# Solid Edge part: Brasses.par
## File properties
Author: Vicky Raina
Template: normal.par
Last saved by: Administrator
Revision: 4
Application: Solid Edge
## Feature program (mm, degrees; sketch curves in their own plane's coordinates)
sketch for "unnamed RevolvedProtrusion 1" plane through (0, 0, 0) normal (0, -1, 0) x-axis (1, 0, 0)
  line (-32.5, 0) -> (-32.5, 32)
  line (-32.5, 32) -> (-23, 32)
  line (-23, 32) -> (-23, 24)
  line (-23, 24) -> (-14, 24)
  line (-14, 24) -> (-14, 22)
  line (-14, 22) -> (14, 22)
  line (14, 22) -> (14, 24)
  line (14, 24) -> (23, 24)
  line (23, 24) -> (23, 32)
  line (23, 32) -> (32.5, 32)
  line (32.5, 32) -> (32.5, 0)
  line (32.5, 0) -> (-32.5, 0)
revolve "unnamed RevolvedProtrusion 1" add finite 360 deg
sketch for "unnamed Protrusion 1" plane through (0, 0, 0) normal (0, 0, 1) x-axis (1, 0, 0)
  circle centre (0, 0) radius 4
extrude "unnamed Protrusion 1" add finite 30 along -normal
sketch for "unnamed Hole 1" plane through (0, 0, -30) normal (0, 0, -1) x-axis (1, 0, 0)
  hole centre (0, 0) bore radius 3
hole "unnamed Hole 1" through
sketch for "unnamed Hole 2" plane through (32.5, 0, 0) normal (1, 0, 0) x-axis (0, 1, 0)
  hole centre (0, 0) bore radius 16
hole "unnamed Hole 2" through
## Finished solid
Body 1: solid body, 16 faces, 18 edges, 0 vertices.
  Faces by surface: cylinder 9, plane 7
  Edges by curve: circle 14, intersection 4
Bounding box of the edges (mm): 65.000 x 64.000 x 64.000, from (-32.5, -32, -32) to (32.5, 32, 32).
Cylindrical faces by radius (mm): R3 x2, R4 x1, R16 x1, R22 x1, R24 x2, R32 x2
Planar faces by outward normal: +x 3, -x 3, -z 1
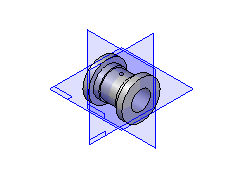
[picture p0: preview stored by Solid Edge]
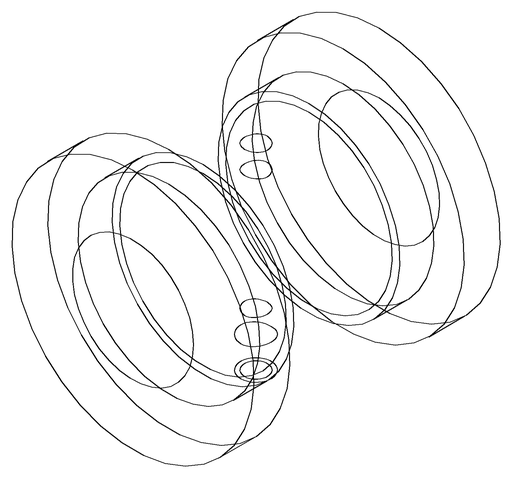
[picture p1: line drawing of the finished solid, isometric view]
